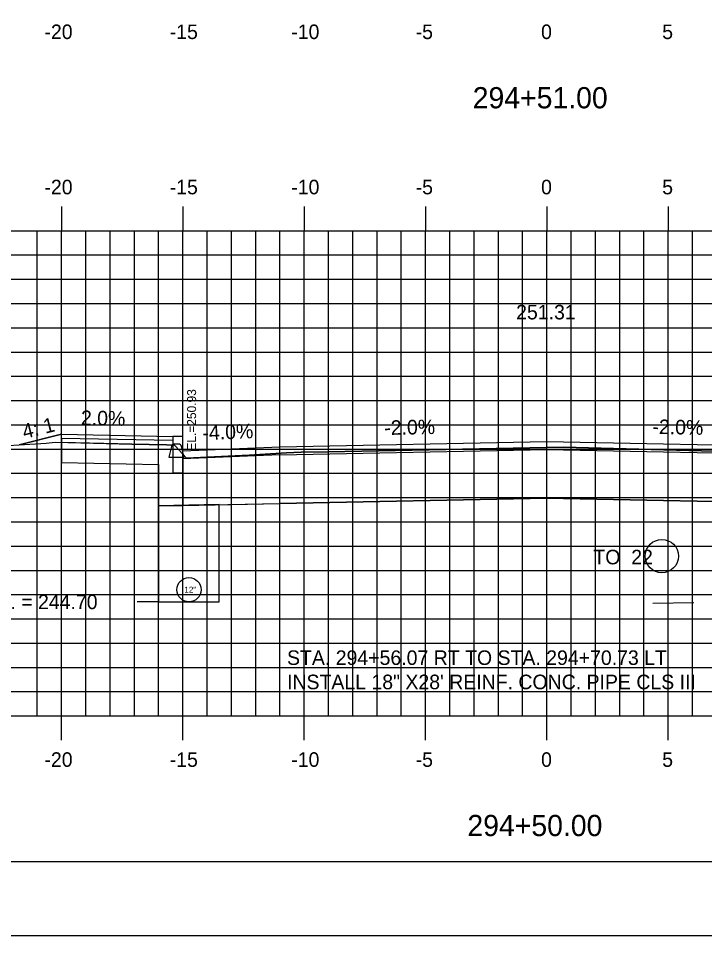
# Model space of a CAD drawing. Extents: x 859352 to 859522, y 366268 to 366378.
# Drawn here: x 859413.35 to 859441.63, y 366268.18 to 366305.99 of the extents above; entities that cross this region are included whole.
import ezdxf

# ---------------------------------------------------------------- set-up
doc = ezdxf.new("R2010")
doc.units = 0
for name, color, linetype in [('ANNOTATION', 7, 'Continuous'), ('BORDER', 7, 'Continuous'), ('D_Curb_Type_1_Lt', 7, 'Continuous'), ('D_Drainage_Text', 7, 'Continuous'), ('D_Roadway_Centerline', 7, 'Continuous'), ('D_Roadway_Centerline_Text', 7, 'Continuous'), ('D_Roadway_Edge_Shoulder', 7, 'Continuous'), ('D_Roadway_FinishedGrade', 7, 'Continuous'), ('D_Roadway_Sidewalks_Paved', 7, 'Continuous'), ('D_Roadway_SubGrade', 7, 'Continuous'), ('D_Text_Standard', 7, 'Continuous'), ('H_V ANNOTATION', 7, 'Continuous'), ('JUNK COM EXC', 7, 'Continuous'), ('JUNK FILL', 7, 'Continuous'), ('junk strct exc', 7, 'Continuous'), ('MAJOR', 7, 'Continuous'), ('MINOR', 7, 'Continuous'), ('PDRAIN', 7, 'Continuous'), ('PLOT BOUNDARY', 7, 'Continuous'), ('S_Curb_Type_3', 7, 'Continuous'), ('S_Roadway_Centerline', 7, 'Continuous')]:
    doc.layers.add(name, color=color, linetype=linetype)

msp = doc.modelspace()

# ---------------------------------------------------------------- linework, layer by layer
at = {"layer": 'ANNOTATION'}
msp.add_line((859441.182, 366281.892), (859439.492, 366281.874), dxfattribs=at)
at = {"layer": 'BORDER'}
msp.add_line((859360.13, 366271.236), (859520.13, 366271.236), dxfattribs=at)
at = {"layer": 'D_Curb_Type_1_Lt'}
msp.add_lwpolyline([(859419.713, 366288.752), (859419.713, 366287.252), (859420.129, 366287.252), (859420.129, 366288.752)], close=True, dxfattribs=at)
at = {"layer": 'D_Drainage_Text'}
msp.add_circle((859439.865, 366283.825), 0.687, dxfattribs=at)
at = {"layer": 'D_Roadway_Centerline'}
msp.add_lwpolyline([(859424.129, 366288.328), (859435.129, 366288.548), (859446.129, 366288.328)], dxfattribs=at)
at = {"layer": 'D_Roadway_Edge_Shoulder'}
msp.add_lwpolyline([(859420.129, 366288.168), (859424.129, 366288.328), (859435.129, 366288.548), (859446.129, 366288.328), (859450.121, 366288.169)], dxfattribs=at)
at = {"layer": 'D_Roadway_FinishedGrade'}
msp.add_line((859413.382, 366288.408), (859415.124, 366288.843), dxfattribs=at)
at = {"layer": 'D_Roadway_Sidewalks_Paved'}
msp.add_lwpolyline([(859415.124, 366288.843), (859419.713, 366288.752), (859419.713, 366288.585), (859415.124, 366288.677)], close=True, dxfattribs=at)
at = {"layer": 'D_Roadway_SubGrade'}
msp.add_lwpolyline([(859415.124, 366288.677), (859415.124, 366287.676), (859419.129, 366287.596), (859419.129, 366285.895), (859420.129, 366285.915)], dxfattribs=at)
for points in [[(859424.129, 366285.995), (859424.129, 366287.995), (859435.129, 366288.215), (859446.129, 366287.995), (859446.129, 366285.995), (859435.129, 366286.215)], [(859424.129, 366287.995), (859420.129, 366287.835), (859420.129, 366285.915), (859424.129, 366285.995)]]:
    msp.add_lwpolyline(points, close=True, dxfattribs=at)
at = {"layer": 'D_Text_Standard'}
msp.add_lwpolyline([(859419.129, 366281.936), (859418.92, 366281.936), (859418.24, 366281.936)], dxfattribs=at)
msp.add_lwpolyline([(859419.129, 366281.936), (859418.92, 366281.936), (859418.24, 366281.936)], dxfattribs=at)
at = {"layer": 'JUNK COM EXC'}
msp.add_lwpolyline([(859415.124, 366288.509), (859415.124, 366287.676), (859419.129, 366287.596), (859419.129, 366285.895), (859424.129, 366285.995), (859435.129, 366286.215), (859446.129, 366285.995), (859451.129, 366285.895), (859451.129, 366287.577), (859445.548, 366288.061), (859445.111, 366288.071), (859435.808, 366288.308), (859426.117, 366288.123), (859424.997, 366288.101), (859424.392, 366288.075), (859422.855, 366287.987), (859420.57, 366287.867), (859420.271, 366287.854), (859419.808, 366288.366), (859419.782, 366288.389), (859419.446, 366288.403), (859418.024, 366288.437), (859415.124, 366288.509)], dxfattribs=at)
at = {"layer": 'JUNK FILL'}
msp.add_lwpolyline([(859415.129, 366288.509), (859415.129, 366288.843), (859415.124, 366288.843), (859413.382, 366288.408), (859414.498, 366288.475), (859414.863, 366288.516)], close=True, dxfattribs=at)
at = {"layer": 'junk strct exc'}
msp.add_lwpolyline([(859419.129, 366285.895), (859419.129, 366281.936), (859421.629, 366281.936), (859421.629, 366285.945)], close=True, dxfattribs=at)
at = {"layer": 'MAJOR'}
for p, q in [((859415.129, 366298.238), (859415.129, 366297.236)), ((859420.129, 366298.238), (859420.129, 366297.236)), ((859425.129, 366298.238), (859425.129, 366297.236)), ((859430.129, 366298.238), (859430.129, 366297.236)), ((859435.129, 366298.238), (859435.129, 366297.236)), ((859440.129, 366298.238), (859440.129, 366297.236)), ((859365.129, 366297.236), (859505.129, 366297.236)), ((859365.129, 366297.236), (859505.129, 366297.236)), ((859415.129, 366277.236), (859415.129, 366297.236)), ((859420.129, 366277.236), (859420.129, 366297.236)), ((859425.129, 366277.236), (859425.129, 366297.236)), ((859430.129, 366277.236), (859430.129, 366297.236)), ((859435.129, 366277.236), (859435.129, 366297.236)), ((859440.129, 366277.236), (859440.129, 366297.236)), ((859365.129, 366292.236), (859505.129, 366292.236)), ((859365.129, 366287.236), (859505.129, 366287.236)), ((859365.129, 366282.236), (859505.129, 366282.236)), ((859365.129, 366277.236), (859505.129, 366277.236)), ((859365.129, 366277.236), (859505.129, 366277.236)), ((859415.129, 366276.234), (859415.129, 366277.236)), ((859420.129, 366276.234), (859420.129, 366277.236)), ((859425.129, 366276.234), (859425.129, 366277.236)), ((859430.129, 366276.234), (859430.129, 366277.236)), ((859435.129, 366276.234), (859435.129, 366277.236)), ((859440.129, 366276.234), (859440.129, 366277.236))]:
    msp.add_line(p, q, dxfattribs=at)
at = {"layer": 'MINOR'}
for p, q in [((859414.129, 366277.236), (859414.129, 366297.236)), ((859416.129, 366277.236), (859416.129, 366297.236)), ((859417.129, 366277.236), (859417.129, 366297.236)), ((859418.129, 366277.236), (859418.129, 366297.236)), ((859419.129, 366277.236), (859419.129, 366297.236)), ((859421.129, 366277.236), (859421.129, 366297.236)), ((859422.129, 366277.236), (859422.129, 366297.236)), ((859423.129, 366277.236), (859423.129, 366297.236)), ((859424.129, 366277.236), (859424.129, 366297.236)), ((859426.129, 366277.236), (859426.129, 366297.236)), ((859427.129, 366277.236), (859427.129, 366297.236)), ((859428.129, 366277.236), (859428.129, 366297.236)), ((859429.129, 366277.236), (859429.129, 366297.236)), ((859431.129, 366277.236), (859431.129, 366297.236)), ((859432.129, 366277.236), (859432.129, 366297.236)), ((859433.129, 366277.236), (859433.129, 366297.236)), ((859434.129, 366277.236), (859434.129, 366297.236)), ((859436.129, 366277.236), (859436.129, 366297.236)), ((859437.129, 366277.236), (859437.129, 366297.236)), ((859438.129, 366277.236), (859438.129, 366297.236)), ((859439.129, 366277.236), (859439.129, 366297.236)), ((859441.129, 366277.236), (859441.129, 366297.236)), ((859365.129, 366296.236), (859505.129, 366296.236)), ((859365.129, 366295.236), (859505.129, 366295.236)), ((859365.129, 366294.236), (859505.129, 366294.236)), ((859365.129, 366293.236), (859505.129, 366293.236)), ((859365.129, 366291.236), (859505.129, 366291.236)), ((859365.129, 366290.236), (859505.129, 366290.236)), ((859365.129, 366289.236), (859505.129, 366289.236)), ((859365.129, 366288.236), (859505.129, 366288.236)), ((859365.129, 366286.236), (859505.129, 366286.236)), ((859365.129, 366285.236), (859505.129, 366285.236)), ((859365.129, 366284.236), (859505.129, 366284.236)), ((859365.129, 366283.236), (859505.129, 366283.236)), ((859365.129, 366281.236), (859505.129, 366281.236)), ((859365.129, 366280.236), (859505.129, 366280.236)), ((859365.129, 366279.236), (859505.129, 366279.236)), ((859365.129, 366278.236), (859505.129, 366278.236))]:
    msp.add_line(p, q, dxfattribs=at)
at = {"layer": 'PDRAIN'}
msp.add_lwpolyline([(859419.129, 366285.895), (859419.129, 366281.936), (859421.629, 366281.936), (859421.629, 366285.945)], dxfattribs=at)
msp.add_circle((859420.379, 366282.436), 0.5, dxfattribs=at)
at = {"layer": 'PLOT BOUNDARY'}
msp.add_lwpolyline([(859352.036, 366268.177), (859522.036, 366268.177), (859522.036, 366378.177), (859352.036, 366378.177)], close=True, dxfattribs=at)
at = {"layer": 'S_Curb_Type_3'}
for points in [[(859419.655, 366288.342), (859419.552, 366287.898), (859420.177, 366287.898), (859420.075, 366288.342)], [(859419.953, 366288.439), (859419.777, 366288.439)]]:
    msp.add_lwpolyline(points, dxfattribs=at)
for centre, start, end in [((859419.777, 366288.314), 90, 167.0054), ((859419.953, 366288.314), 12.9946, 90)]:
    msp.add_arc(centre, 0.125, start, end, dxfattribs=at)
at = {"layer": 'S_Roadway_Centerline'}
msp.add_lwpolyline([(859406.448, 366287.989), (859414.498, 366288.475), (859414.863, 366288.516), (859418.024, 366288.437), (859419.446, 366288.403), (859419.782, 366288.389), (859419.808, 366288.366), (859420.271, 366287.854), (859420.57, 366287.867), (859422.855, 366287.987), (859424.392, 366288.075), (859424.997, 366288.101), (859426.117, 366288.123), (859435.808, 366288.308), (859445.111, 366288.071), (859445.548, 366288.061), (859452.194, 366287.484), (859452.255, 366287.481), (859453.169, 366287.475), (859453.829, 366288.077), (859453.867, 366288.1), (859456.735, 366287.987), (859463.938, 366287.704), (859477.165, 366287.052)], dxfattribs=at)

# ---------------------------------------------------------------- texts
at = {"layer": 'ANNOTATION'}
for s, rotation, p in [('2.0%', 358.8542, (859415.922, 366289.228)), ('4: 1', 14.0362, (859413.595, 366288.651)), ('-4.0%', 2.2906, (859420.945, 366288.602)), ('-2.0%', 1.1458, (859428.432, 366288.814)), ('-2.0%', 358.8542, (859439.472, 366288.862))]:
    msp.add_text(s, height=0.6, rotation=rotation, dxfattribs=at).set_placement(p)
at = {"layer": 'D_Drainage_Text'}
for s, p in [('TO  22', (859437.043, 366283.484)), ('STA. 294+56.07 RT TO STA. 294+70.73 LT', (859424.42, 366279.336)), ('INSTALL 18" X28\' REINF. CONC. PIPE CLS III', (859424.42, 366278.336))]:
    msp.add_text(s, height=0.6, dxfattribs=at).set_placement(p)
at = {"layer": 'D_Roadway_Centerline_Text'}
msp.add_text('251.31', height=0.6, dxfattribs=at).set_placement((859433.861, 366293.58))
at = {"layer": 'D_Text_Standard'}
msp.add_text(' EL.=250.93', height=0.36848, rotation=90, dxfattribs=at).set_placement((859420.672, 366288.033))
msp.add_text('ELEV. = 244.70', height=0.6, dxfattribs=at).set_placement((859410.969, 366281.636))
at = {"layer": 'H_V ANNOTATION'}
for s, height, p in [('-20', 0.6, (859414.423, 366305.136)), ('-15', 0.6, (859419.586, 366305.136)), ('-10', 0.6, (859424.594, 366305.136)), ('-5', 0.6, (859429.72, 366305.136)), ('0', 0.6, (859434.888, 366305.136)), ('5', 0.6, (859439.88, 366305.136)), ('294+51.00', 0.875, (859432.071, 366302.28)), ('-20', 0.6, (859414.423, 366298.736)), ('-15', 0.6, (859419.586, 366298.736)), ('-10', 0.6, (859424.594, 366298.736)), ('-5', 0.6, (859429.72, 366298.736)), ('0', 0.6, (859434.888, 366298.736)), ('5', 0.6, (859439.88, 366298.736)), ('-20', 0.6, (859414.423, 366275.136)), ('-15', 0.6, (859419.586, 366275.136)), ('-10', 0.6, (859424.594, 366275.136)), ('-5', 0.6, (859429.72, 366275.136)), ('0', 0.6, (859434.888, 366275.136)), ('5', 0.6, (859439.88, 366275.136)), ('294+50.00', 0.875, (859431.852, 366272.28))]:
    msp.add_text(s, height=height, dxfattribs=at).set_placement(p)
at = {"layer": 'PDRAIN'}
msp.add_text('12"', height=0.25, dxfattribs=at).set_placement((859420.188, 366282.312))
at = {"layer": 'S_Roadway_Centerline'}
for s, p in [('C', (859435.802, 366288.308)), ('L', (859435.808, 366288.301))]:
    msp.add_text(s, height=0.0146, dxfattribs=at).set_placement(p)

doc.saveas('drawing.dxf')
